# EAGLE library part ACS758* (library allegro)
Thermally Enhanced, Fully Integrated, Hall Effect-Based Linear Current Sensor with 100 micro Ohm Current Conductor display layer 49 Reference in BRD and place VIAs on circles Source: http://www.allegromicro.com/en/Products/Part_Numbers/0758/0758.pdf
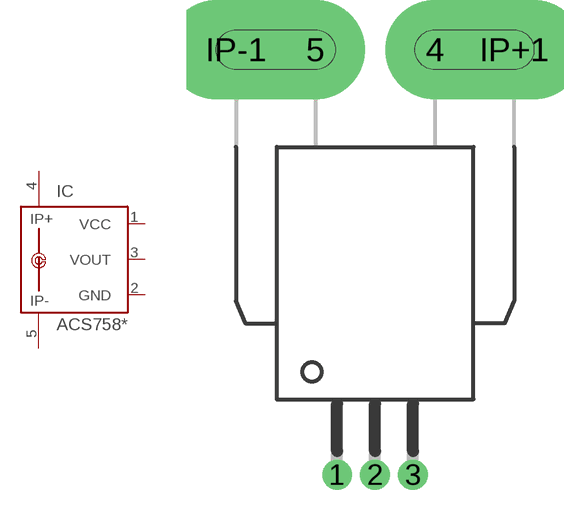
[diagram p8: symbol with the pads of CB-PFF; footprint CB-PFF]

Designator prefix IC

## ACS758ECB-200B-PFF-T (MPN: ACS758ECB-200B-PFF-T; OC_FARNELL: 1718993; OC_NEWARK: 04R7127), ACS758KCB-150B-PFF-T (MPN: ACS758KCB-150B-PFF-T; OC_FARNELL: 1718995; OC_NEWARK: 04R7129), ACS758LCB-050B-PFF-T (MPN: ACS758LCB-050B-PFF-T; OC_FARNELL: 1718997; OC_NEWARK: 04R7131), ACS758LCB-100B-PFF-T (MPN: ACS758LCB-100B-PFF-T; OC_FARNELL: 1718998; OC_NEWARK: 04R7132)  [CB-PFF]
1  VCC  pwr
2  GND  pwr
3  VOUT  out
4  IP+  pas
5  IP-  pas
IP+1  IP+1  in
IP-1  IP-1  in

## Footprint CB-PFF (pad centres in mm)
5-pin module, leadform PFF In BRD, display layer 49 Reference and place VIAs with drill = 0,5mm on circles In DRC, set Clearance same signals PAD to VIA = 0 Source: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
drill 0.8 pad 1.5 round: 1 -1.91,-21.4; 2 0,-21.4; 3 1.91,-21.4
drill 2 pad 5 offset: 4 3,0; 5 -3,0
drill 2 pad 4 offset: IP+1 7,0; IP-1 -7,0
